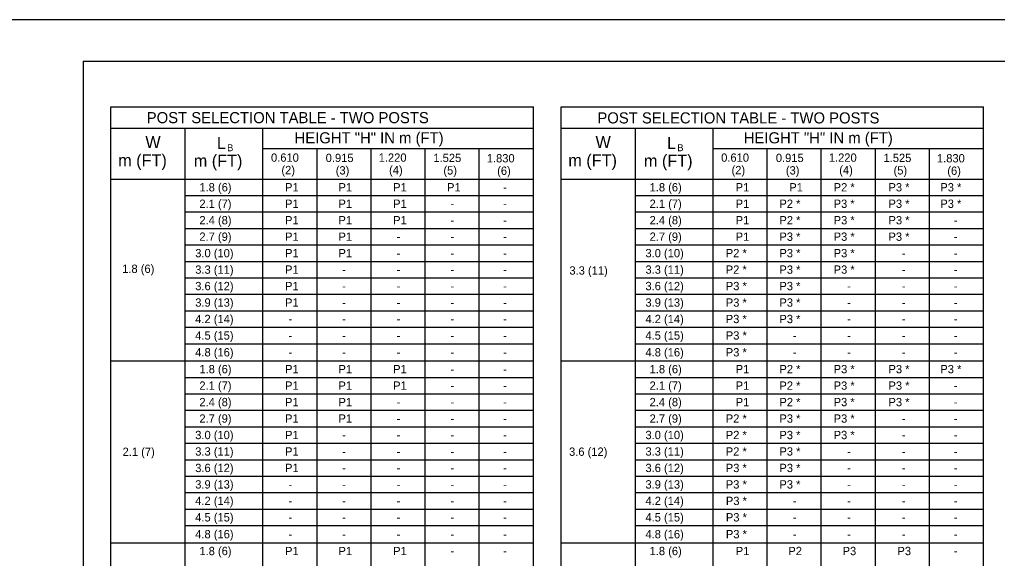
# Model space of a CAD drawing. Extents: x -1958 to 628, y -879 to 309.
# Drawn here: x -1100.4 to -747.7, y 115 to 309.4 of the extents above; entities that cross this region are included whole.
import ezdxf

# ---------------------------------------------------------------- set-up
doc = ezdxf.new("R2010")
doc.units = 0
for name, color, linetype in [('1', 7, 'Continuous'), ('2', 7, 'Continuous'), ('30', 7, 'Continuous'), ('PLT-BNDY', 7, 'Continuous')]:
    doc.layers.add(name, color=color, linetype=linetype)

msp = doc.modelspace()

# ---------------------------------------------------------------- linework, layer by layer
at = {"layer": '1'}
for p, q in [((-1077.39, 294.44), (-291.39, 294.44)), ((-1077.39, 294.44), (-1077.39, -269.56)), ((-1067.39, 251.9), (-1067.39, 277.92)), ((-1067.39, 277.92), (-915.04, 277.92)), ((-915.04, 251.9), (-915.04, 277.92)), ((-905.04, 251.9), (-905.04, 277.92)), ((-905.04, 277.92), (-752.69, 277.92)), ((-752.69, 251.9), (-752.69, 277.92)), ((-1067.39, 270.25), (-915.04, 270.25)), ((-1040.58, 251.9), (-1040.58, 270.25)), ((-1012.58, 251.9), (-1012.58, 270.25)), ((-905.04, 270.25), (-752.69, 270.25)), ((-878.24, -76.15), (-878.24, 270.25)), ((-850.23, -76.15), (-850.23, 270.25)), ((-993.07, 251.9), (-993.07, 262.9)), ((-973.56, 251.9), (-973.56, 262.9)), ((-954.05, 251.9), (-954.05, 262.9)), ((-934.55, 251.9), (-934.55, 262.9)), ((-830.72, -76.15), (-830.72, 262.9)), ((-811.22, -76.15), (-811.22, 262.9)), ((-791.71, -76.15), (-791.71, 262.9)), ((-772.2, -76.15), (-772.2, 262.9)), ((-1067.39, -76.15), (-1067.39, 251.9)), ((-1067.39, 251.9), (-915.04, 251.9)), ((-974.24, 251.9), (-938.6, 251.9)), ((-915.04, -76.15), (-915.04, 251.9)), ((-905.04, -76.15), (-905.04, 251.9)), ((-905.04, 251.9), (-752.69, 251.9)), ((-752.69, -76.15), (-752.69, 251.9)), ((-878.24, 245.96), (-752.69, 245.96)), ((-878.24, 240.02), (-752.69, 240.02)), ((-878.24, 234.08), (-752.69, 234.08)), ((-878.24, 228.14), (-752.69, 228.14)), ((-878.24, 222.2), (-752.69, 222.2)), ((-878.24, 216.26), (-752.69, 216.26)), ((-878.24, 210.32), (-752.69, 210.32)), ((-878.24, 204.38), (-752.69, 204.38)), ((-878.24, 198.44), (-752.69, 198.44)), ((-878.24, 192.5), (-752.69, 192.5)), ((-905.04, 186.29), (-752.69, 186.29)), ((-878.24, 180.35), (-752.69, 180.35)), ((-878.24, 174.41), (-752.69, 174.41)), ((-878.24, 168.47), (-752.69, 168.47)), ((-878.24, 162.53), (-752.69, 162.53)), ((-776.25, 162.53), (-752.69, 162.53)), ((-878.24, 156.59), (-752.69, 156.59)), ((-878.24, 150.65), (-752.69, 150.65)), ((-878.24, 144.71), (-752.69, 144.71)), ((-776.25, 144.71), (-752.69, 144.71)), ((-878.24, 138.77), (-752.69, 138.77)), ((-878.24, 132.83), (-752.69, 132.83)), ((-878.24, 126.89), (-752.69, 126.89)), ((-905.04, 120.68), (-752.69, 120.68))]:
    msp.add_line(p, q, dxfattribs=at)
at = {"layer": '2'}
for p, q in [((-1012.58, 262.9), (-915.04, 262.9)), ((-850.23, 262.9), (-752.69, 262.9)), ((-1040.58, -76.15), (-1040.58, 251.9)), ((-1012.58, -76.15), (-1012.58, 251.9)), ((-993.07, -76.15), (-993.07, 251.9)), ((-973.56, -76.15), (-973.56, 251.9)), ((-954.05, -76.15), (-954.05, 251.9)), ((-934.55, -76.15), (-934.55, 251.9)), ((-1040.58, 245.96), (-915.04, 245.96)), ((-974.24, 245.96), (-938.6, 245.96)), ((-938.6, 245.96), (-915.04, 245.96)), ((-1040.58, 240.02), (-915.04, 240.02)), ((-974.24, 240.02), (-938.6, 240.02)), ((-938.6, 240.02), (-915.04, 240.02)), ((-1040.58, 234.08), (-915.04, 234.08)), ((-974.24, 234.08), (-938.6, 234.08)), ((-938.6, 234.08), (-915.04, 234.08)), ((-1040.58, 228.14), (-915.04, 228.14)), ((-974.24, 228.14), (-938.6, 228.14)), ((-938.6, 228.14), (-915.04, 228.14)), ((-1040.58, 222.2), (-915.04, 222.2)), ((-974.24, 222.2), (-938.6, 222.2)), ((-938.6, 222.2), (-915.04, 222.2)), ((-1040.58, 216.26), (-915.04, 216.26)), ((-974.24, 216.26), (-938.6, 216.26)), ((-938.6, 216.26), (-915.04, 216.26)), ((-1040.58, 210.32), (-915.04, 210.32)), ((-974.24, 210.32), (-938.6, 210.32)), ((-938.6, 210.32), (-915.04, 210.32)), ((-1040.58, 204.38), (-915.04, 204.38)), ((-974.24, 204.38), (-938.6, 204.38)), ((-938.6, 204.38), (-915.04, 204.38)), ((-1040.58, 198.44), (-915.04, 198.44)), ((-974.24, 198.44), (-938.6, 198.44)), ((-938.6, 198.44), (-915.04, 198.44)), ((-1040.58, 192.5), (-915.04, 192.5)), ((-974.24, 192.5), (-938.6, 192.5)), ((-938.6, 192.5), (-915.04, 192.5)), ((-1067.39, 186.29), (-915.04, 186.29)), ((-974.24, 186.29), (-938.6, 186.29)), ((-938.6, 186.29), (-915.04, 186.29)), ((-1040.58, 180.35), (-915.04, 180.35)), ((-974.24, 180.35), (-938.6, 180.35)), ((-938.6, 180.35), (-915.04, 180.35)), ((-1040.58, 174.41), (-915.04, 174.41)), ((-974.24, 174.41), (-938.6, 174.41)), ((-938.6, 174.41), (-915.04, 174.41)), ((-1040.58, 168.47), (-915.04, 168.47)), ((-974.24, 168.47), (-938.6, 168.47)), ((-938.6, 168.47), (-915.04, 168.47)), ((-1040.58, 162.53), (-915.04, 162.53)), ((-974.24, 162.53), (-938.6, 162.53)), ((-938.6, 162.53), (-915.04, 162.53)), ((-1040.58, 156.59), (-915.04, 156.59)), ((-974.24, 156.59), (-938.6, 156.59)), ((-938.6, 156.59), (-915.04, 156.59)), ((-1040.58, 150.65), (-915.04, 150.65)), ((-974.24, 150.65), (-938.6, 150.65)), ((-938.6, 150.65), (-915.04, 150.65)), ((-1040.58, 144.71), (-915.04, 144.71)), ((-974.24, 144.71), (-938.6, 144.71)), ((-938.6, 144.71), (-915.04, 144.71)), ((-1040.58, 138.77), (-915.04, 138.77)), ((-974.24, 138.77), (-938.6, 138.77)), ((-938.6, 138.77), (-915.04, 138.77)), ((-1040.58, 132.83), (-915.04, 132.83)), ((-974.24, 132.83), (-938.6, 132.83)), ((-1040.58, 126.89), (-915.04, 126.89)), ((-974.24, 126.89), (-938.6, 126.89)), ((-1067.39, 120.68), (-915.04, 120.68)), ((-974.24, 120.68), (-938.6, 120.68))]:
    msp.add_line(p, q, dxfattribs=at)
at = {"layer": 'PLT-BNDY'}
msp.add_lwpolyline([(-1117.39, 309.44), (-276.39, 309.44), (-276.39, -284.56), (-1117.39, -284.56)], close=True, dxfattribs=at)

# ---------------------------------------------------------------- texts
at = {"layer": '1'}
for s, height, p in [('POST SELECTION TABLE - TWO POSTS', 4.003, (-1054.49, 272.05)), ('POST SELECTION TABLE - TWO POSTS', 4.003, (-891.97, 271.96)), ('HEIGHT "H" IN m (FT)', 4.003, (-1001.19, 264.77)), ('HEIGHT "H" IN m (FT)', 4.003, (-839.19, 264.77)), ('W', 4.37, (-1054.99, 263.05)), ('L', 4.3, (-1029.19, 262.77)), ('W', 4.37, (-892.64, 263.05)), ('L', 4.3, (-866.85, 262.77)), ('m (FT)', 4.375, (-1064.8, 256.48)), ('B', 2.5, (-1025.49, 261.94)), ('0.610', 3, (-1009.68, 258.14)), ('0.915', 3, (-989.96, 258.03)), ('1.220', 3, (-970.84, 258.14)), ('1.525', 3, (-951.12, 258.03)), ('m (FT)', 4.375, (-902.46, 256.48)), ('B', 2.5, (-863.14, 261.94)), ('0.610', 3, (-847.33, 258.14)), ('0.915', 3, (-827.61, 258.03)), ('1.220', 3, (-808.49, 258.14)), ('1.525', 3, (-788.77, 258.03)), ('m (FT)', 4.375, (-1037.54, 256.31)), ('1.830', 3, (-931.86, 257.9)), ('m (FT)', 4.375, (-875.19, 256.31)), ('1.830', 3, (-769.51, 257.9)), ('(2)', 3, (-1005.93, 253.64)), ('(3)', 3, (-986.34, 253.53)), ('(4)', 3, (-967.1, 253.64)), ('(5)', 3, (-947.51, 253.53)), ('(6)', 3, (-928.12, 253.4)), ('(2)', 3, (-843.58, 253.64)), ('(3)', 3, (-824, 253.53)), ('(4)', 3, (-804.75, 253.64)), ('(5)', 3, (-785.16, 253.53)), ('(6)', 3, (-765.77, 253.4)), ('2.1 (7)', 3, (-873.14, 241.49)), ('P1', 3, (-842.1, 241.49)), ('P2 *', 3, (-826.33, 241.49)), ('P3 *', 3, (-806.76, 241.49)), ('P3 *', 3, (-786.99, 241.49)), ('P3 *', 3, (-768.29, 241.49)), ('2.4 (8)', 3, (-873.14, 235.55)), ('P1', 3, (-842.1, 235.55)), ('P2 *', 3, (-826.33, 235.55)), ('P3 *', 3, (-806.76, 235.55)), ('P3 *', 3, (-786.99, 235.55)), ('-', 3, (-763.44, 235.55)), ('2.7 (9)', 3, (-873.14, 229.61)), ('P1', 3, (-842.1, 229.61)), ('P3 *', 3, (-826.33, 229.61)), ('P3 *', 3, (-806.76, 229.61)), ('P3 *', 3, (-786.99, 229.61)), ('-', 3, (-763.44, 229.61)), ('3.0 (10)', 3, (-874.64, 223.67)), ('P2 *', 3, (-845.67, 223.67)), ('P3 *', 3, (-826.33, 223.67)), ('P3 *', 3, (-806.76, 223.67)), ('-', 3, (-782.14, 223.67)), ('-', 3, (-763.44, 223.67)), ('3.3 (11)', 3, (-874.64, 217.73)), ('P2 *', 3, (-845.67, 217.73)), ('P3 *', 3, (-826.33, 217.73)), ('P3 *', 3, (-806.76, 217.73)), ('-', 3, (-782.14, 217.73)), ('-', 3, (-763.44, 217.73)), ('3.6 (12)', 3, (-874.64, 211.79)), ('P3 *', 3, (-845.67, 211.79)), ('P3 *', 3, (-826.33, 211.79)), ('-', 3, (-801.91, 211.79)), ('-', 3, (-782.14, 211.79)), ('-', 3, (-763.44, 211.79)), ('3.9 (13)', 3, (-874.64, 205.85)), ('P3 *', 3, (-845.67, 205.85)), ('P3 *', 3, (-826.33, 205.85)), ('-', 3, (-801.91, 205.85)), ('-', 3, (-782.14, 205.85)), ('-', 3, (-763.44, 205.85)), ('4.2 (14)', 3, (-874.64, 199.91)), ('P3 *', 3, (-845.67, 199.91)), ('P3 *', 3, (-826.33, 199.91)), ('-', 3, (-801.91, 199.91)), ('-', 3, (-782.14, 199.91)), ('-', 3, (-763.44, 199.91)), ('4.5 (15)', 3, (-874.64, 193.97)), ('P3 *', 3, (-845.67, 193.97)), ('-', 3, (-821.48, 193.97)), ('-', 3, (-801.91, 193.97)), ('-', 3, (-782.14, 193.97)), ('-', 3, (-763.44, 193.97)), ('4.8 (16)', 3, (-874.64, 187.9)), ('P3 *', 3, (-845.67, 187.9)), ('-', 3, (-821.48, 187.9)), ('-', 3, (-801.91, 187.9)), ('-', 3, (-782.14, 187.9)), ('-', 3, (-763.44, 187.9)), ('1.8 (6)', 3, (-873.14, 181.82)), ('P1', 3, (-842.1, 181.82)), ('P2 *', 3, (-826.33, 181.82)), ('P3 *', 3, (-806.76, 181.82)), ('P3 *', 3, (-786.99, 181.82)), ('P3 *', 3, (-768.29, 181.82)), ('2.1 (7)', 3, (-873.14, 175.88)), ('P1', 3, (-842.1, 175.88)), ('P2 *', 3, (-826.33, 175.88)), ('P3 *', 3, (-806.76, 175.88)), ('P3 *', 3, (-786.99, 175.88)), ('-', 3, (-763.44, 175.88)), ('2.4 (8)', 3, (-873.14, 169.94)), ('P1', 3, (-842.1, 169.94)), ('P2 *', 3, (-826.33, 169.94)), ('P3 *', 3, (-806.76, 169.94)), ('P3 *', 3, (-786.99, 169.94)), ('-', 3, (-763.44, 169.94)), ('2.7 (9)', 3, (-873.14, 164)), ('P2 *', 3, (-845.67, 164)), ('P3 *', 3, (-826.33, 164)), ('P3 *', 3, (-806.76, 164)), ('-', 3, (-782.14, 164)), ('-', 3, (-763.44, 164)), ('3.0 (10)', 3, (-874.64, 158.06)), ('P2 *', 3, (-845.67, 158.06)), ('P3 *', 3, (-826.33, 158.06)), ('P3 *', 3, (-806.76, 158.06)), ('-', 3, (-782.14, 158.06)), ('-', 3, (-763.44, 158.06)), ('3.6 (12)', 3, (-902.19, 152.04)), ('3.3 (11)', 3, (-874.64, 152.12)), ('P2 *', 3, (-845.67, 152.12)), ('P3 *', 3, (-826.33, 152.12)), ('-', 3, (-801.91, 152.12)), ('-', 3, (-782.14, 152.12)), ('-', 3, (-763.44, 152.12)), ('3.6 (12)', 3, (-874.64, 146.18)), ('P3 *', 3, (-845.67, 146.18)), ('P3 *', 3, (-826.33, 146.18)), ('-', 3, (-801.91, 146.18)), ('-', 3, (-782.14, 146.18)), ('-', 3, (-763.44, 146.18)), ('3.9 (13)', 3, (-874.64, 140.24)), ('P3 *', 3, (-845.67, 140.24)), ('P3 *', 3, (-826.33, 140.24)), ('-', 3, (-801.91, 140.24)), ('-', 3, (-782.14, 140.24)), ('-', 3, (-763.44, 140.24)), ('4.2 (14)', 3, (-874.64, 134.3)), ('P3 *', 3, (-845.63, 134.3)), ('-', 3, (-821.48, 134.3)), ('-', 3, (-801.91, 134.3)), ('-', 3, (-782.14, 134.3)), ('-', 3, (-763.44, 134.3)), ('4.5 (15)', 3, (-874.64, 128.36)), ('P3 *', 3, (-845.63, 128.36)), ('-', 3, (-821.48, 128.36)), ('-', 3, (-801.91, 128.36)), ('-', 3, (-782.14, 128.36)), ('-', 3, (-763.44, 128.36)), ('4.8 (16)', 3, (-874.64, 122.29)), ('P3 *', 3, (-845.63, 122.29)), ('-', 3, (-821.48, 122.29)), ('-', 3, (-801.91, 122.29)), ('-', 3, (-782.14, 122.29)), ('-', 3, (-763.44, 122.29)), ('1.8 (6)', 3, (-873.14, 116.21)), ('P1', 3, (-842.06, 116.21)), ('P2', 3, (-823.1, 116.21)), ('P3', 3, (-803.53, 116.21)), ('P3', 3, (-783.76, 116.21)), ('-', 3, (-763.44, 116.21))]:
    msp.add_text(s, height=height, dxfattribs=at).set_placement(p)
at = {"layer": '2'}
for s, p in [('2.1 (7)', (-1035.51, 241.49)), ('P1', (-1004.62, 241.49)), ('P1', (-985.35, 241.49)), ('P1', (-965.64, 241.49)), ('-', (-944.91, 241.49)), ('-', (-925.97, 241.49)), ('2.4 (8)', (-1035.51, 235.55)), ('P1', (-1004.62, 235.55)), ('P1', (-985.35, 235.55)), ('P1', (-965.64, 235.55)), ('-', (-944.91, 235.55)), ('-', (-925.97, 235.55)), ('2.7 (9)', (-1035.51, 229.61)), ('P1', (-1004.62, 229.61)), ('P1', (-985.35, 229.61)), ('-', (-964.36, 229.61)), ('-', (-944.91, 229.61)), ('-', (-925.97, 229.61)), ('3.0 (10)', (-1037.01, 223.67)), ('P1', (-1004.62, 223.67)), ('P1', (-985.35, 223.67)), ('-', (-964.36, 223.67)), ('-', (-944.91, 223.67)), ('-', (-925.97, 223.67)), ('3.3 (11)', (-1037.01, 217.73)), ('P1', (-1004.62, 217.73)), ('-', (-984.07, 217.73)), ('-', (-964.36, 217.73)), ('-', (-944.91, 217.73)), ('-', (-925.97, 217.73)), ('3.6 (12)', (-1037.01, 211.79)), ('P1', (-1004.62, 211.79)), ('-', (-984.07, 211.79)), ('-', (-964.36, 211.79)), ('-', (-944.91, 211.79)), ('-', (-925.97, 211.79)), ('3.9 (13)', (-1037.01, 205.85)), ('P1', (-1004.62, 205.85)), ('-', (-984.07, 205.85)), ('-', (-964.36, 205.85)), ('-', (-944.91, 205.85)), ('-', (-925.97, 205.85)), ('4.2 (14)', (-1037.01, 199.91)), ('-', (-1003.34, 199.91)), ('-', (-984.07, 199.91)), ('-', (-964.36, 199.91)), ('-', (-944.91, 199.91)), ('-', (-925.97, 199.91)), ('4.5 (15)', (-1037.01, 193.97)), ('-', (-1003.34, 193.97)), ('-', (-984.07, 193.97)), ('-', (-964.36, 193.97)), ('-', (-944.91, 193.97)), ('-', (-925.97, 193.97)), ('4.8 (16)', (-1037.01, 187.9)), ('-', (-1003.34, 187.9)), ('-', (-984.07, 187.9)), ('-', (-964.36, 187.9)), ('-', (-944.91, 187.9)), ('-', (-925.97, 187.9)), ('1.8 (6)', (-1035.51, 181.82)), ('P1', (-1004.62, 181.82)), ('P1', (-985.35, 181.82)), ('P1', (-965.64, 181.82)), ('-', (-944.91, 181.82)), ('-', (-925.97, 181.82)), ('2.1 (7)', (-1035.51, 175.88)), ('P1', (-1004.62, 175.88)), ('P1', (-985.35, 175.88)), ('P1', (-965.64, 175.88)), ('-', (-944.91, 175.88)), ('-', (-925.97, 175.88)), ('2.4 (8)', (-1035.51, 169.94)), ('P1', (-1004.62, 169.94)), ('P1', (-985.35, 169.94)), ('-', (-964.36, 169.94)), ('-', (-944.91, 169.94)), ('-', (-925.97, 169.94)), ('2.7 (9)', (-1035.51, 164)), ('P1', (-1004.62, 164)), ('P1', (-985.35, 164)), ('-', (-964.36, 164)), ('-', (-944.91, 164)), ('-', (-925.97, 164)), ('3.0 (10)', (-1037.01, 158.06)), ('P1', (-1004.62, 158.06)), ('-', (-984.07, 158.06)), ('-', (-964.36, 158.06)), ('-', (-944.91, 158.06)), ('-', (-925.97, 158.06)), ('3.3 (11)', (-1037.01, 152.12)), ('2.1 (7)', (-1063.2, 152.01)), ('P1', (-1004.62, 152.12)), ('-', (-984.07, 152.12)), ('-', (-964.36, 152.12)), ('-', (-944.91, 152.12)), ('-', (-925.97, 152.12)), ('3.6 (12)', (-1037.01, 146.18)), ('P1', (-1004.62, 146.18)), ('-', (-984.07, 146.18)), ('-', (-964.36, 146.18)), ('-', (-944.91, 146.18)), ('-', (-925.97, 146.18)), ('3.9 (13)', (-1037.01, 140.24)), ('-', (-1003.34, 140.24)), ('-', (-984.07, 140.24)), ('-', (-964.36, 140.24)), ('-', (-944.91, 140.24)), ('-', (-925.97, 140.24)), ('4.2 (14)', (-1037.01, 134.3)), ('-', (-1003.34, 134.3)), ('-', (-984.07, 134.3)), ('-', (-964.36, 134.3)), ('-', (-944.91, 134.3)), ('-', (-925.97, 134.3)), ('4.5 (15)', (-1037.01, 128.36)), ('-', (-1003.34, 128.36)), ('-', (-984.07, 128.36)), ('-', (-964.36, 128.36)), ('-', (-944.91, 128.36)), ('-', (-925.97, 128.36)), ('4.8 (16)', (-1037.01, 122.29)), ('-', (-1003.34, 122.29)), ('-', (-984.07, 122.29)), ('-', (-964.36, 122.29)), ('-', (-944.91, 122.29)), ('-', (-925.97, 122.29)), ('1.8 (6)', (-1035.51, 116.21)), ('P1', (-1004.62, 116.21)), ('P1', (-985.35, 116.21)), ('P1', (-965.64, 116.21)), ('-', (-944.91, 116.21)), ('-', (-925.97, 116.21))]:
    msp.add_text(s, height=3, dxfattribs=at).set_placement(p)
at = {"layer": '30'}
for s, p in [('1.8 (6)', (-1035.51, 247.43)), ('P1', (-1004.62, 247.43)), ('P1', (-985.35, 247.43)), ('P1', (-965.64, 247.43)), ('P1', (-946.19, 247.43)), ('1.8 (6)', (-873.14, 247.43)), ('P1', (-842.1, 247.43)), ('P1', (-822.76, 247.43)), ('P2 *', (-806.76, 247.43)), ('P3 *', (-786.99, 247.43)), ('P3 *', (-768.29, 247.43)), ('-', (-925.97, 247.43)), ('1.8 (6)', (-1063.35, 218.03)), ('3.3 (11)', (-902.06, 217.41))]:
    msp.add_text(s, height=3, dxfattribs=at).set_placement(p)

doc.saveas('drawing.dxf')
